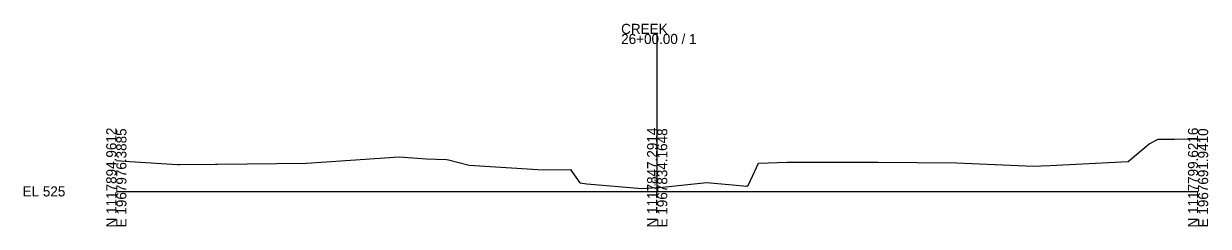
# Model space of a CAD drawing. Extents: x 9974 to 10303, y 9990 to 19550.
# Drawn here: x 9974.3 to 10302.8, y 15490.3 to 15546.6 of the extents above; entities that cross this region are included whole.
import ezdxf

# ---------------------------------------------------------------- set-up
doc = ezdxf.new("R2010")
doc.units = 0
for name, color, linetype in [('Level 10', 7, 'Continuous'), ('Level 60', 7, 'Continuous'), ('Level 63', 7, 'Continuous')]:
    doc.layers.add(name, color=color, linetype=linetype)

msp = doc.modelspace()

# ---------------------------------------------------------------- linework, layer by layer
at = {"layer": 'Level 60'}
for p, q in [((10286.44, 15513.17), (10288.94, 15514.52)), ((10288.94, 15514.52), (10293.48, 15514.48)), ((10293.48, 15514.48), (10297.07, 15514.57)), ((10297.07, 15514.57), (10300, 15514.56)), ((10280.61, 15508.31), (10286.44, 15513.17)), ((10000, 15508.57), (10003.78, 15508.33)), ((10003.78, 15508.33), (10016.98, 15507.44)), ((10016.98, 15507.44), (10017.51, 15507.43)), ((10017.51, 15507.43), (10027.54, 15507.57)), ((10027.54, 15507.57), (10028.02, 15507.55)), ((10028.02, 15507.55), (10052.71, 15507.82)), ((10052.71, 15507.82), (10058.2, 15508.19)), ((10058.2, 15508.19), (10078.48, 15509.55)), ((10078.48, 15509.55), (10086.03, 15509.06)), ((10086.03, 15509.06), (10091.61, 15508.83)), ((10091.61, 15508.83), (10092.16, 15508.76)), ((10092.16, 15508.76), (10097.85, 15507.27)), ((10097.85, 15507.27), (10118.33, 15506.01)), ((10175.28, 15501.84), (10178.1, 15507.81)), ((10178.1, 15507.81), (10186.07, 15508.12)), ((10186.07, 15508.12), (10203.01, 15508.15)), ((10203.01, 15508.15), (10211.2, 15508.12)), ((10211.2, 15508.12), (10233.01, 15507.89)), ((10233.01, 15507.89), (10252.2, 15507.09)), ((10252.2, 15507.09), (10254.05, 15507.05)), ((10254.05, 15507.05), (10258.88, 15507.22)), ((10258.88, 15507.22), (10280.61, 15508.31)), ((10118.33, 15506.01), (10125.98, 15506.06)), ((10125.98, 15506.06), (10126.34, 15505.57)), ((10126.34, 15505.57), (10128.58, 15502.41)), ((10128.58, 15502.41), (10130.47, 15502.11)), ((10130.47, 15502.11), (10145.74, 15500.85)), ((10145.74, 15500.85), (10150, 15501.08)), ((10150, 15501.08), (10150.54, 15501.11)), ((10150.54, 15501.11), (10163.76, 15502.47)), ((10163.76, 15502.47), (10171.87, 15501.72)), ((10171.87, 15501.72), (10174.84, 15501.46)), ((10174.84, 15501.46), (10175.28, 15501.84))]:
    msp.add_line(p, q, dxfattribs=at)
at = {"layer": 'Level 63'}
for p, q in [((10150, 15500), (10150, 15543.71)), ((10000, 15500), (10150, 15500)), ((10150, 15500), (10300, 15500))]:
    msp.add_line(p, q, dxfattribs=at)

# ---------------------------------------------------------------- texts
at = {"layer": 'Level 10'}
msp.add_text('526.085', height=0.8, rotation=90, dxfattribs=at).set_placement((10149.9, 15501.58))
at = {"layer": 'Level 63'}
for s, p in [('CREEK', (10140, 15543.71)), ('26+00.00 / 1', (10140, 15540.91)), ('EL 525', (9974, 15498.6))]:
    msp.add_text(s, height=2.8, dxfattribs=at).set_placement(p)
for s, p in [('N 1117894.9612', (10000, 15490)), ('E 1967976.3885', (10002.8, 15490)), ('N 1117847.2914', (10150, 15490)), ('E 1967834.1648', (10152.8, 15490)), ('N 1117799.6216', (10300, 15490)), ('E 1967691.9410', (10302.8, 15490))]:
    msp.add_text(s, height=2.8, rotation=90, dxfattribs=at).set_placement(p)

doc.saveas('drawing.dxf')
